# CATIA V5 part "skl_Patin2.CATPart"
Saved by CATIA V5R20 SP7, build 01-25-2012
Part number: skl_Patin2
Publications: "Axe_Patin2Equerre6", "Axe_Patin2Patin1", "Point.1", "Point.2", "Plan.1", "Corps principal"
Bounding box of the stored display mesh (mm): x 0 to 20, y 0 to 47, z 22 to 111
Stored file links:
  J:\ACHTUNG2\skl_Patin2.CATPart
  J:\cmilovidofIAO\skl_IAO.CATProduct
  J:\ACHTUNG2\skl_IAO2.CATProduct
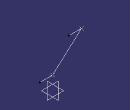
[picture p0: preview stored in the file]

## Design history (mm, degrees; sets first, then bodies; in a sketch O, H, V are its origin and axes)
Set1
  Point1: linked copy from another document
  Point2: linked copy from another document
  Plane1: linked copy from another document
Body1 (main body)
  Line1: type PtPt, FirstPoint Point1, SecondPoint Point2
  Line2: type Normal, RefPoint Point2, RefSkin Plane1, Start 0, End 20
  Line3: type Normal, RefPoint Point1, RefSkin Plane1, Start 0, End 20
